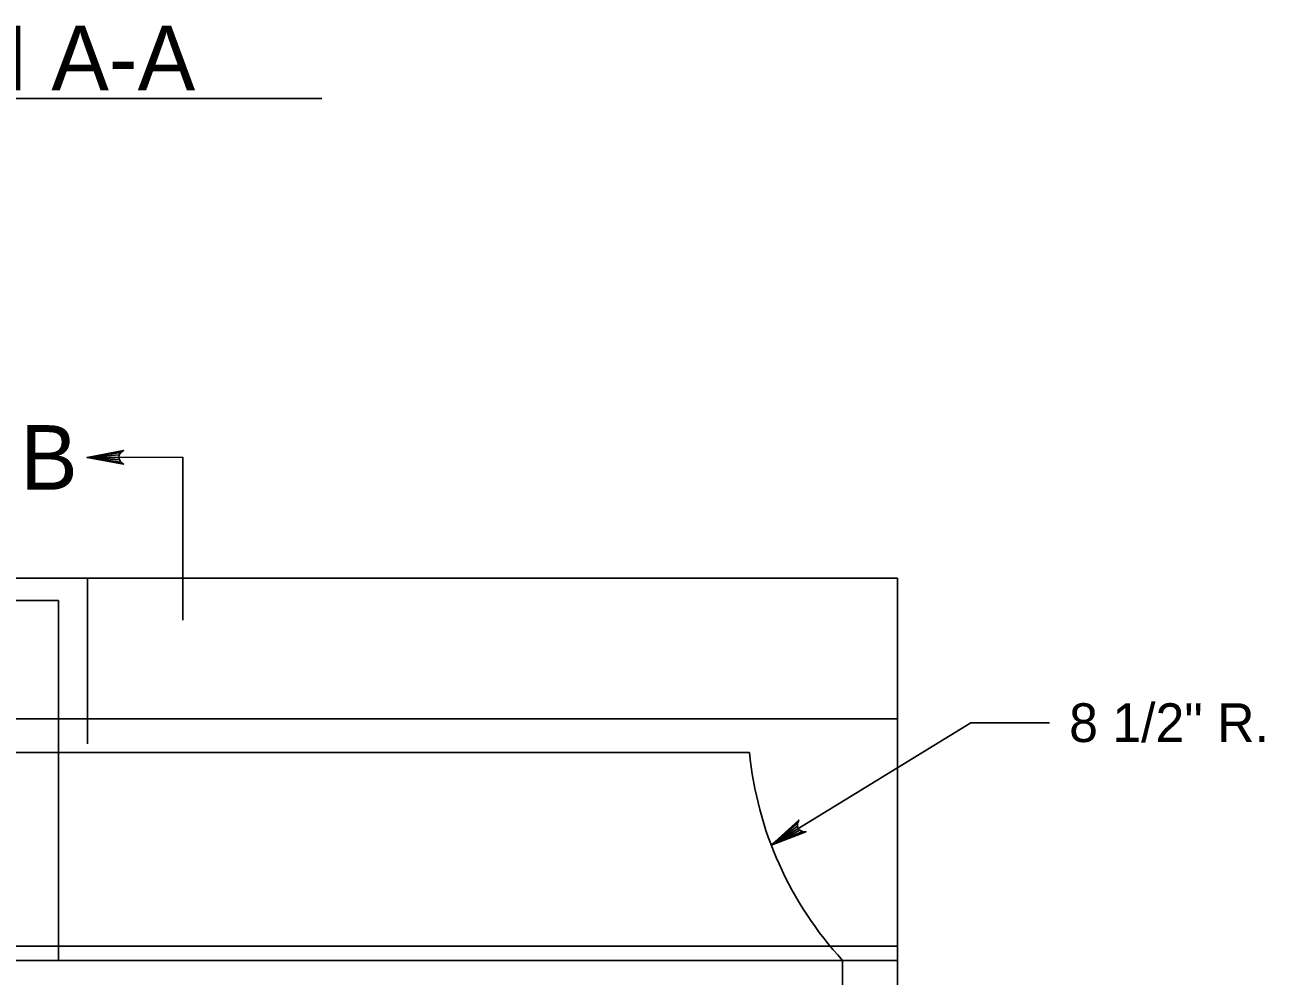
# Model space of a CAD drawing. Extents: x 2.4 to 9.7, y 1.1 to 11.2.
# Drawn here: x 7.421 to 9.341, y 6.481 to 7.955 of the extents above; entities that cross this region are included whole.
import ezdxf

# ---------------------------------------------------------------- set-up
doc = ezdxf.new("R2010")
doc.units = 0
for name, color, linetype in [('DETL-DIMS', 7, 'Continuous'), ('DETL-LINE', 7, 'Continuous'), ('DETL-NOTE', 7, 'Continuous'), ('DETL-TITL', 7, 'Continuous')]:
    doc.layers.add(name, color=color, linetype=linetype)

msp = doc.modelspace()

# ---------------------------------------------------------------- linework, layer by layer
at = {"layer": 'DETL-DIMS'}
for p, q in [((7.666, 7.2849), (7.5175, 7.2845)), ((7.666, 7.2849), (7.666, 7.0325)), ((8.5771, 6.684), (8.8863, 6.8736)), ((8.8863, 6.8736), (9.0083, 6.8736))]:
    msp.add_line(p, q, dxfattribs=at)
for points in [[(7.5175, 7.2845), (7.5739, 7.2953), (7.5696, 7.2922), (7.5673, 7.2884), (7.5667, 7.2846), (7.5674, 7.2809), (7.5696, 7.2771), (7.574, 7.2741), (7.5175, 7.2845), (7.5696, 7.2771), (7.5674, 7.2809), (7.5175, 7.2845), (7.5667, 7.2846), (7.5673, 7.2884), (7.5175, 7.2845), (7.5696, 7.2922)], [(8.5771, 6.684), (8.6198, 6.7226), (8.6176, 6.7177), (8.6177, 6.7133), (8.6191, 6.7097), (8.6216, 6.7069), (8.6255, 6.7048), (8.6308, 6.7045), (8.5771, 6.684), (8.6255, 6.7048), (8.6216, 6.7069), (8.5771, 6.684), (8.6191, 6.7097), (8.6177, 6.7133), (8.5771, 6.684), (8.6176, 6.7177)]]:
    msp.add_lwpolyline(points, dxfattribs=at)
at = {"layer": 'DETL-LINE'}
for p, q in [((8.7729, 7.0975), (6.0058, 7.0975)), ((7.518, 7.0975), (7.518, 6.8408)), ((8.7729, 7.0975), (8.7729, 5.8344)), ((7.3053, 7.063), (7.4734, 7.063)), ((7.4734, 7.063), (7.4734, 6.5054)), ((8.7729, 6.8796), (6.0058, 6.8796)), ((6.2352, 6.8276), (8.5435, 6.8276)), ((6.0058, 6.5276), (8.7729, 6.5276)), ((6.0058, 6.5054), (8.7729, 6.5054)), ((8.6877, 6.5054), (8.6877, 5.2799))]:
    msp.add_line(p, q, dxfattribs=at)
msp.add_arc((9.0944, 6.8807), 0.5534, 185.5118, 222.6988, dxfattribs=at)
at = {"layer": 'DETL-TITL'}
msp.add_line((6.8186, 7.8406), (7.8811, 7.8406), dxfattribs=at)

# ---------------------------------------------------------------- texts
at = {"layer": 'DETL-NOTE'}
msp.add_text('8 1/2" R.', height=0.06, dxfattribs=at).set_placement((9.0386, 6.8436))
at = {"layer": 'DETL-TITL'}
for s, p in [('SECTION A-A', (6.8305, 7.8532)), ('B', (7.4137, 7.2345))]:
    msp.add_text(s, height=0.1, dxfattribs=at).set_placement(p)

doc.saveas('drawing.dxf')
